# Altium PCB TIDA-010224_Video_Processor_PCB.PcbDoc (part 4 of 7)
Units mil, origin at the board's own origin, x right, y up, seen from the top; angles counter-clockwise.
Board outline 2355.46 x 4164 mil, 10 copper layers (L1-Top Layer, L2-GND, L3-SIG1, L4-GND, L5-PWR, L6-PWR, L7-GND, L8-SIG2, L9-GND, L10-Bottom Layer), stack 62.2 mil thick; 508 components, 274 nets, 3619 pads, 705 vias.
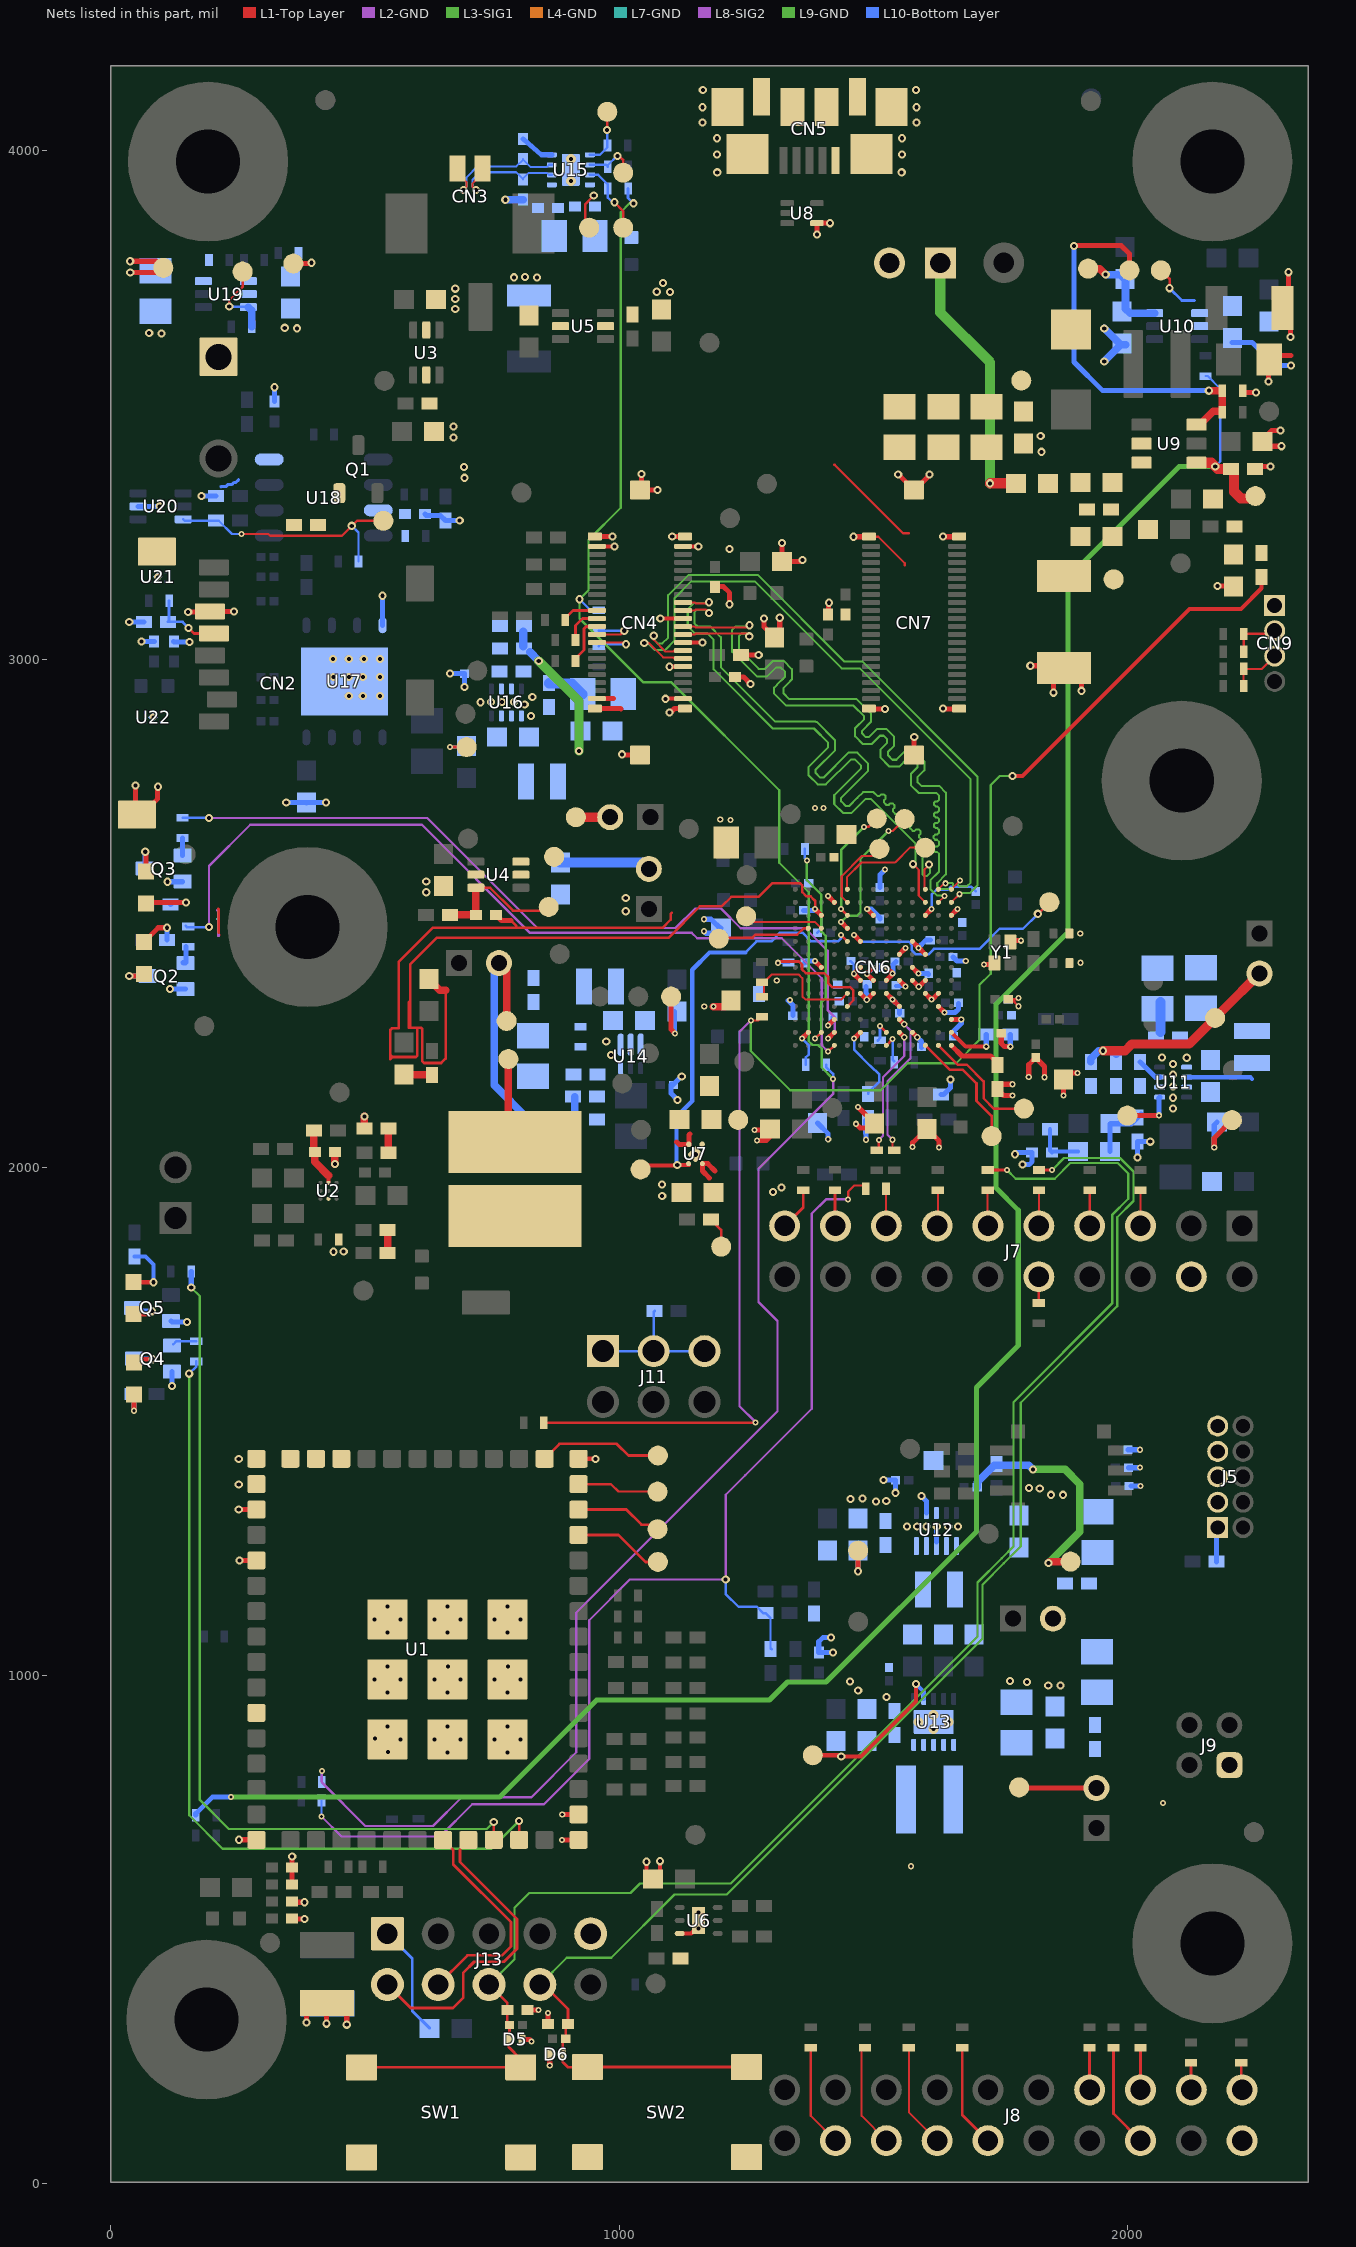
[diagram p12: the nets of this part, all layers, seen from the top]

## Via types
v1: diameter 16, hole 8, L1-Top Layer to L10-Bottom Layer, tented both sides, 414 vias
v2: diameter 12, hole 6, L1-Top Layer to L10-Bottom Layer, tented both sides, 243 vias
v3: diameter 19.68, hole 7.87, L1-Top Layer to L10-Bottom Layer, 44 vias
v4: diameter 14, hole 6, L1-Top Layer to L10-Bottom Layer, tented both sides, 2 vias
v5: diameter 16, hole 8, L1-Top Layer to L10-Bottom Layer, tented top, 1 vias
v6: diameter 20, hole 10, L1-Top Layer to L10-Bottom Layer, tented both sides, 1 vias

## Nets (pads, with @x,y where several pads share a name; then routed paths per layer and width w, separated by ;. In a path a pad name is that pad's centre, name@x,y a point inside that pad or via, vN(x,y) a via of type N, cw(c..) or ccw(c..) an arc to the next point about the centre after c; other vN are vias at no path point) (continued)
DEBUG_MAC: J13.4 U1.50 | length 439.2
  L1-Top Layer w5.5: J13.4@644,392 701.49,449.49 769.49,449.49 787,467 787,515 673.5,628.5 673.5,656.46 U1.50@653.26,676.7
DEBUG_NWP: J13.2 U1.51 | length 618.2
  L1-Top Layer w5.5: J13.2@544,392 590,346 672.8,346 693.4,366.6 693.4,415.4 715,437 773.51,437 799,462.49 799,521 687,633 687,658 703.26,674.26 U1.51@703.26,676.7
EFUSE_SW: CN6.J9 EN.1 U7.3 | length 855
  L1-Top Layer w5: v2(1436.77,2457) CN6.J9@1449,2444.77
  L1-Top Layer w8: EN.1@1042.21,1995.96 1049.79,2003.53 1113.53,2003.53 v1(1114.36,2004.36) U7.3@1137.4,2004.36
  L10-Bottom Layer w5: 1248.59,2423.13 1270.24,2444.77 1299.76,2444.77 1316.78,2461.79 1360.75,2461.79 1377.77,2444.77 1406.28,2444.77 1406.55,2445.04 1416.9,2445.04 1417.18,2444.77 1430.77,2444.77 1436.77,2450.77 v2(1436.77,2457)
  L10-Bottom Layer w8: v1(1114.36,2004.36) 1113.24,2003.24 1113.24,2099.78 1143.84,2130.39 1143.84,2388.85 1178.12,2423.13 1248.59,2423.13
FB: C55.2 FB.1 R67.1 R68.1 R72.2 U9.3
FREQ: FREQ.1 R78.2 R79.1 U9.6 | length 794.6
  L1-Top Layer w10: v1(1895.05,3813.16) 1895.88,3814 1987.56,3814 2004.08,3797.49 FREQ.1@2004.08,3765
  L1-Top Layer w15: U9.6@2136.13,3461.4 2142.4,3461.4 2169,3488 2187,3488 R78.2@2187,3528.24 v1(2160.24,3528.24)
  L10-Bottom Layer w10: v1(1895.05,3813.16) 1895,3584.87 1951.63,3528.24 v1(2160.24,3528.24)
GND: C3.2 C4.1 C5.1 C6.1 C7.2 C8.1 C11.2 C13.2 C14.2 C16.2 C17.1 C18.2 C19.1 C20.1 C21.2 C22.1 C23.2 C24.2 C25.2 C26.2 C27.2 C28.2 C29.2 C30.2 C31.1 C33.2 C34.2 C35.2 C36.2 C37.2 C38.2 C39.1 C40.2 C41.2 C42.2 C43.2 C44.2 C45.2 C46.2 C47.1 C48.1 C49.1 C50.1 C52.2 C53.1 C54.1 C56.1 C57.2 C58.2 C59.1 C60.1 C61.1 C62.2 C63.2 C64.2 C65.2 C66.2 C67.2 C68.2 C70.2 C71.1 C72.2 C73.2 C74.1 C75.1 C76.1 C77.1 C78.1 C79.1 C80.1 C81.1 C82.1 C83.1 C84.1 C85.1 C86.1 C87.2 C88.1 C89.2 C90.1 C91.1 C92.1 C93.2 C94.1 C95.2 C96.1 C97.1 C98.1 C99.1 C100.1 C101.1 C102.2 C103.1 C104.2 C105.1 C106.1 C107.1 C108.1 C109.2 C110.2 C111.2 C112.2 C113.2 C115.1 C116.2 C117.2 C118.1 C119.2 C120.2 C121.2 C123.1 C124.2 C125.2 C126.1 C127.2 C128.2 C129.1 C130.1 C131.1 C132.2 C133.2 C134.1 CN2.6 CN2.9 CN4.1 CN4.2 CN4.20 CN4.26 CN4.32 CN4.39 CN4.40 CN4.MP1 CN4.MP2 CN4.MP3 CN4.MP4 CN4.MP5 CN4.MP6 CN5.5 CN5.6 CN5.7 CN5.8 CN5.9 CN5.10 CN5.11 CN5.12 CN5.13 CN6.B4 CN6.C1 CN6.C10 CN6.D2 CN6.D5 CN6.E2 CN6.E3 CN6.E6 CN6.E7 CN6.E8 CN6.F3 CN6.F4 CN6.F5 CN6.F6 CN6.F7 CN6.F8 CN6.G4 CN6.G6 CN6.G7 CN6.G8 CN6.G11 CN6.H3 CN6.H5 CN6.J4 CN6.L1 CN6.L3 CN6.L7 CN6.L11 CN6.M10 CN7.MP1 CN7.MP2 CN7.MP3 CN7.MP4 CN7.MP5 CN7.MP6 CN9.1 D5.2 D6.2 J1.1 J5.3 J5.5 J5.7 J5.9 J7.22 J8.20 J9.1 J13.9 MK1.2 Q2.2 Q3.2 Q4.2 Q5.2 R4.1 R7.2 R33.1 R61.2 R64.1 R77.1 R78.1 R93.1 R94.1 R96.2 R97.2 R98.2 R106.2 R108.1 R110.1 R112.1 R113.1 R114.1 R116.2 R118.2 R120.1 R132.1 R135.2 R141.1 R148.1 R149.2 R172.1 SW1.2 SW1.4 SW2.2 SW2.4 U1.1 U1.2 U1.16 U1.25 U1.26 U1.27 U1.28 U1.29 U1.30 U1.32 U1.38 U1.43 U1.55@780.43,874.5 U1.56@780.43,992.61 U1.57@780.43,1110.72 U1.58@662.31,874.5 U1.59@662.31,992.61 U1.60@662.31,1110.72 U1.61@544.2,874.5 U1.62@544.2,992.61 U1.63@544.2,1110.72 U2.A2 U3.2 U3.5 U4.2 U5.2 U5.5 U6.3 U6.7 U7.2 U7.5 U8.4 U9.2 U10.2 U11.3 U11.5 U12.2 U12.3 U12.8 U13.8 U13.11@1619,908.87 U14.4@1003.12,2241.27 U15.4 U15.9@905,3962.97 U16.3 U16.5 U17.4 U17.9 U18.4 U19.2 U20.2 U21.5 U22.5 Y1.2 Y1.4 | length 9091.1
  L1-Top Layer w5: 210.89,2508.6 211.7,2507.79 211.7,2461.83 ; 658.57,2348.87 658.57,2214.22 649.72,2205.37 616.33,2205.37 612.35,2209.35 612.35,2272.46 610.26,2274.55 601.29,2274.55 ; 787,2485.76 797.97,2474.79 ; 1103.37,2500.68 1101.55,2498.86 1101.55,2487.7 1085.1,2471.25 632.81,2471.25 566.59,2405.03 566.59,2273.54 552.8,2273.54 549.75,2270.49 549.75,2221.16 ; v2(1385.59,2508.18) 1385.59,2524.27 1383.75,2526.11 1383.75,2526.31 1377,2533.06 1368.73,2533.06 1360.24,2541.55 1360.24,2554.77 1355.65,2559.36 1301.35,2559.36 1274.36,2532.37 1220.6,2532.37 1201.82,2513.59 1158.59,2513.59 1096.75,2451.75 640.89,2451.75 588.57,2399.43 588.57,2327.35 ; 1423.78,3382.57 1558.99,3247.36 1569.48,3247.36 ; CN7.MP1@1491.66,3240.91 1509.78,3240.91 1562,3188.69 1562,3185 ; C48.1@1765.5,2331 C48.1@1771.97,2331 ; v2(1785.97,2317) C48.1@1771.97,2331 ; v2(1785.97,2333.06) 1783.91,2331 C48.1@1771.97,2331 ; 549.75,2217.6 549.75,2221.16 ; 549.75,2217.6 549.75,2213.1 553.78,2217.13 ; 549.75,2217.6 550.22,2217.13 553.78,2217.13 ; 549.75,2221.16 553.78,2217.13 ; 553.78,2217.13 600.14,2217.13 602.95,2219.94 602.95,2272.89 601.29,2274.55 ; 588.57,2327.35 588.57,2275.59 589.55,2274.61 ; 588.57,2327.35 586.09,2324.87 586.09,2274.61 589.55,2274.61 ; 589.55,2274.61 594.88,2274.61 594.94,2274.55 601.29,2274.55
  L1-Top Layer w8: U1.16@920.19,1426.63 953.38,1426.63 v1(953.69,1426.31) ; CN4.1@959.29,3221.73 v1@990.66,3221.73 ; v1(1054.07,633.72) 1054.07,611.73 C24.2@1066.36,599.44 1080.65,613.72 v1(1080.65,634.72) ; v1(1081,3080) CN4.20@1128.58,3080 ; v1@1091.58,2922.52 CN4.40@1125.65,2922.52 ; v1(1099,2985) 1128.07,2985 CN4.32@1128.58,2985.51 ; U6.3@1119.17,492.36 1141.88,492.36 1150.95,501.44 U6.7@1156.77,501.44 ; CN4.26@1128.58,3032.76 v1(1164.17,3032.76) ; CN4.2@1128.58,3221.73 v1(1155.73,3221.73)
  L1-Top Layer w9: CN4.39@959.29,2922.52 989.41,2922.52
  L1-Top Layer w10: v1(48,2751.14) 48,2694.59 54.76,2687.83 92,2725.07 92,2748.42 v1(92.5,2748.93) ; v1(152,3093) 193.68,3093 CN2.6@194.65,3093.97 ; CN2.6@194.68,3094 v1(242,3094) ; v1(251.46,1326.67) 285,1326.67 285.67,1326 U1.30@286.07,1326.41 ; v1(252,677) 283.37,677 285,675.37 U1.43@286.33,676.7 ; v1(252.79,1226.67) U1.32@286.33,1226.67 ; C6.1@356,521.67 356.67,521 v1(381,521) ; C4.1@356,587 C4.1@356,589 356,619.67 356.67,619 v1(356.67,644) ; C5.1@366.36,554.33 366.69,554 v1(380.69,554) ; v1(385,317) 385,330.96 C7.2@395.97,341.93 ; v1(424,315) 424,332.78 429,337.78 C7.2@424.85,341.93 ; C7.2@457,341.93 464.02,334.91 v1(464.02,313) ; C19.1@757.25,2496.79 768.28,2485.76 787,2485.76 ; D5.2@808.42,284 823.88,284 v2(827.88,280) ; C20.1@819.37,342 v2(841.37,342) ; C22.1@860,314 v2(860,336) ; v2(863.41,233) D6.2@863.41,255 ; v2(887.81,676.45) U1.1@919.93,676.45 ; v2(888.07,726.67) U1.2@920.19,726.67 ; CN4.MP3@955.35,2902.83 1002.61,2902.83 1003.4,2902.04 ; CN4.MP1@955.35,3241.42 v1@986.73,3241.42 ; v1(1005.3,2812.79) 1005.3,2811.3 CN4.MP6@1041,2811.3 ; v1@1043.93,3364.33 1043.93,3332.95 v1@1075.31,3332.95 ; v1(1099,2895.06) 1101.06,2895.06 1108.84,2902.83 CN4.MP4@1129.58,2902.83 CN4.MP4@1132.51,2902.83 ; v1@1104.53,3241.42 CN4.MP2@1129.58,3241.42 CN4.MP2@1132.51,3241.42 ; 1113.24,2049.71 1117.64,2045.31 U7.2@1137.2,2045.31 1137.2,2063.56 1139.1,2065.46 ; C30.2@1189,3142.63 1205.37,3142.63 1217.46,3130.54 1217,3130.07 1217.46,3129.61 v1(1217.46,3108) ; C29.2@1228.16,2964.71 1244.93,2964.71 v1(1258.41,2951.23) ; C28.2@1239.62,3008 v1(1274.57,3008) ; v2(1266,2073.7) 1294.7,2073.7 1296.64,2075.64 C36.2@1297.12,2075.16 1297.12,2060.21 1289.69,2052.79 v2(1271.22,2052.79) ; v1(1284.97,3080) 1284.97,3063.82 C37.2@1299,3049.79 ; C37.2@1305.48,3042.38 1316,3052.9 v1(1316,3081.44) ; v1(1320.47,3228.76) 1320.47,3192.31 C34.2@1320.19,3192.03 1357.87,3192.03 v1(1361.11,3195.27) ; v2(1385.59,2405.82) CN6.G11@1397.82,2393.59 ; v2(1385.59,2508.18) CN6.L11@1397.82,2495.95 ; v1(1389.09,3835.23) U8.4@1389.09,3857.82 v1(1414.95,3857.82) ; C40.2@1409.18,3087.43 1411.83,3090.07 1411.83,3111 v1(1412.68,3111) ; v2(1411.18,2279) CN6.C10@1423.41,2291.23 ; v2(1411.18,2533.77) CN6.M10@1423.41,2521.54 ; v1(1461,3240.91) CN7.MP1@1491.66,3240.91 ; v2(1465.98,2085.73) 1474.48,2077.23 1493,2077.23 C42.2@1502,2086.23 1502,2086.71 v2(1469.98,2118.73) ; CN6.E8@1474.59,2342.41 v2(1487.18,2329.82) ; CN6.F8@1474.59,2368 1462,2380.59 v2(1462,2381) CN6.G8@1474.59,2393.59 ; v2@1487.59,2329.82 CN6.E7@1500.18,2342.41 ; v2(1488.13,2508) CN6.L7@1500.18,2495.95 ; CN7.MP3@1491.66,2902.32 v1@1523.04,2902.32 ; CN6.F7@1500.18,2368 1487.39,2380.8 CN6.G7@1500.18,2393.59 ; CN6.E6@1525.77,2342.41 v2(1538,2330.18) CN6.D5@1551.36,2316.82 ; CN6.F6@1525.77,2368 v2@1538,2380.23 ; CN6.G6@1525.77,2393.59 v2(1538,2381.36) ; v1(1549.08,3363.6) 1580.68,3332 1611,3362.32 v1(1611,3363.6) ; CN6.F5@1551.36,2368 v2(1563.59,2355.77) ; CN6.H5@1551.36,2419.18 v2(1563.59,2431.41) ; CN6.B4@1576.95,2265.64 v2(1586.59,2256) ; CN6.F4@1576.95,2368 v2(1589.54,2355.41) ; CN6.G4@1576.95,2393.59 v2(1589.18,2381.36) ; CN6.J4@1576.95,2444.77 1589.04,2432.69 1589.14,2432.69 1589.14,2432.58 CN6.H3@1602.54,2419.18 ; v2(1577.53,2040.23) 1577.53,2048.67 1604.8,2075.95 C44.2@1606.08,2075.95 1613.25,2068.79 1613.03,2068.79 1629.53,2052.29 v2(1629.53,2038.73) ; CN7.MP6@1580.24,2810.79 CN7.MP6@1580.24,2811.3 1580.24,2846.56 v1(1580.68,2847) ; v2@1589.95,2355.41 CN6.F3@1602.54,2368 ; CN6.E3@1602.54,2342.41 v2(1614.77,2330.18) ; CN6.L3@1602.54,2495.95 v2(1614.77,2508.18) ; v2@1615.91,2330.18 CN6.E2@1628.13,2342.41 ; CN6.D2@1628.13,2316.82 v2(1640.36,2304.59) ; v1@1637.45,2902.32 CN7.MP4@1668.82,2902.32 ; v1@1637.45,3240.91 CN7.MP2@1668.82,3240.91 ; CN6.C1@1653.72,2291.23 v2(1673.1,2291.23) ; CN6.L1@1653.72,2495.95 v2(1665.95,2508.18) ; v2(1718,2399) 1735.03,2399 Y1.2@1738.36,2402.33 ; C47.1@1751.83,2263.64 1751.83,2243.88 1758.29,2237.42 v2(1769.62,2237.42) ; Y1.4@1769.86,2443.67 1772.19,2446 v2(1791,2446) ; v2(1774,2141.44) 1756.28,2141.44 R61.2@1744,2153.72 1753.79,2163.52 v2(1774,2163.52) ; v2(1806,2177.79) 1806,2202.09 C50.1@1814.64,2210.73 ; v1(1809,2987) 1835.03,2987 R64.1@1839,2990.97 ; C50.1@1820,2216.09 1820,2215.27 1837,2198.27 v2(1837,2177.37) ; v1(1855,2934) 1855,2960 R64.1@1863,2968 ; v2(1874,2141.44) C52.2@1874,2172.67 1887.28,2185.95 v2(1902,2185.95) ; v1(1909.62,2937.76) 1909.62,2961.62 R64.1@1914,2966 ; v1(2177.02,3144) 2207.65,3144 C60.1@2208.65,3142.99 C60.1@2208.65,3142.17 ; R78.1@2227,3525 v1(2252.82,3525) ; R77.1@2244.62,3379 v1(2282,3379) ; v1(2278,3546) 2278,3588.17 C58.2@2279,3589.17 2287.17,3597.34 2321.9,3597.34 ; v1(2301,3450) 2284,3450 2267,3433 2265.5,3433 2279.5,3419 v1(2303,3419) ; v1(2316.77,3761.44) 2316.77,3702.59 2305,3690.81 2304.96,3673.04 2321,3657 v1(2321,3634)
  L1-Top Layer w15: v1(440.68,2006.69) C8.1@440.68,2030 ; C11.2@498.76,2076.76 v1(498.76,2100.07) ; C17.1@625.96,2370.29 647.38,2348.87 658.57,2348.87 ; v2(1185.71,2316.23) 1208,2316.23 C33.2@1220.46,2328.69
  L2-GND w5: 209.39,2505.74 211.61,2503.52 211.61,2455.38
  L4-GND w6: 211.61,2493.46 211.61,2457.4 212.19,2456.82
  L7-GND w6: 209.89,2488.73 211.76,2486.86 211.76,2460.13 211.61,2460.28
  L9-GND w6: 211.04,2487.29 211.61,2486.72 211.61,2462.28
  L10-Bottom Layer w5: v2(1385.59,2508.18) 1397.59,2496.18 1397.59,2469.52 C101.1@1390.07,2462 ; C97.1@1455.01,2406 1455.07,2406 1462,2399.07 v2(1462,2381) ; v2(1614.77,2508.18) 1614.77,2536.79 1624.25,2546.27 1646.95,2546.27 1652.4,2551.73 1693.27,2551.73 C76.1@1702,2542.99
  L10-Bottom Layer w6: 216.23,3339.22 216.47,3339.46 225.97,3339.46 229.89,3343.38 237.44,3343.38 241.82,3347.76 245.68,3347.76 251.21,3353.29
  L10-Bottom Layer w8: v1(385,317) 385,330.96 409.1,355.06 C127.2@427.63,355.06 ; v1(424,315) 424,343.14 429,348.14 424.85,352.29 C127.2@427.63,355.06 ; v1(464.02,313) 464.02,344.76 453.72,355.06 C127.2@427.63,355.06 ; C88.1@1544.99,2357 1562.36,2357 v2(1563.59,2355.77)
  L10-Bottom Layer w10: v1(36,3073.44) C132.2@64.9,3073.44 ; U20.2@53.49,3300.76 v1(95.45,3300.76) ; v1(60,3035) 85.4,3035 C134.1@85.52,3035.12 ; v1(111,2562) 140.72,2562 Q3.2@141.13,2562.41 ; v1(116.44,2351) 146.82,2351 Q2.2@147,2350.82 ; Q5.2@118.4,1697.71 120.11,1696 v1(150,1696) ; v1(120.09,1569.72) Q4.2@120.09,1598.12 ; C131.1@123,3034.68 123.68,3034 v1(154.54,3034) ; v1(178.16,3321.35) R172.1@206.57,3321.35 ; C130.1@322,3507 v1(322,3535) ; v1(345,2718) 384.03,2718 C128.2@384.52,2717.5 385.02,2718 v1(423,2718) ; U17.4@534.52,3066.67 v1(534.52,3124.77) ; C126.1@617.94,3285.41 620.48,3282.87 648.17,3282.87 C125.2@658.25,3272.79 v1(686.25,3272.79) ; v1(667,2972) 695.48,2972 696,2971.48 R149.2@695.52,2971 v1(695.52,2945.19) ; C124.2@811,4023.37 846.87,3992.5 U15.4@867.6,3992.5 ; v1(1115,2132.62) 1101.99,2145.63 1101.99,2162.5 1103.54,2164.04 1105.58,2162 1122.72,2179.14 v1(1123.23,2179.14) ; v2(1167.01,2488.19) 1180.88,2488.19 C109.2@1199.29,2469.78 ; v2(1167.26,2464.59) 1171.11,2460.73 1190.23,2460.73 C109.2@1199.29,2469.78 ; C109.2@1200.5,2471 C109.2@1199.29,2469.78 ; v2@1332.79,2328.37 1341.74,2319.42 C106.1@1341.74,2298.62 ; C108.1@1362.99,2505.82 1383.23,2505.82 v2(1385.59,2508.18) ; C107.1@1365,2402.01 1368.81,2405.82 v2(1385.59,2405.82) ; C102.2@1390.52,2087.07 1411.36,2066.23 v2(1411.36,2055.29) ; v2(1411.18,2279) 1421.01,2288.83 C99.1@1421.01,2296 ; v1(1417.16,1074.66) 1400.79,1074.66 1392.79,1066.66 C103.1@1392.79,1045.39 v1(1420.79,1045.39) ; v2(1485.35,2054.32) 1485.35,2066.53 1485.13,2066.75 1485.13,2092.51 R120.1@1490,2097.38 ; C94.1@1485.98,2355.41 1485.98,2342.42 1487.18,2341.22 v2(1487.18,2329.82) ; v2(1488,2380.91) 1500.1,2393.01 C92.1@1512,2393.01 ; v2(1488.13,2508) 1495.79,2508 1496.22,2508.43 1513,2491.65 C91.1@1513,2488.99 ; C90.1@1513.15,2550.49 1513.15,2575.98 v2(1523.04,2585.87) ; v1@1520.6,1384.69 R116.2@1544.01,1384.69 v1(1544.01,1359.68) ; v2(1538,2381.36) 1538.56,2381.93 1538.56,2398.56 C85.1@1545.01,2405 ; C86.1@1551.99,2303 1551.99,2316.19 v2@1538.93,2329.25 ; v2(1586.59,2256) 1594.98,2247.61 C84.1@1594.98,2236 ; v2@1589.14,2432.69 1603.45,2447 C82.1@1612.01,2447 C82.1@1612.48,2447 ; v2(1589.18,2381.36) 1589.3,2381.24 1607.75,2381.24 C83.1@1609,2379.99 ; v1(1594.7,1353.13) 1604.49,1343.34 U12.2@1604.49,1319.65 ; U13.11@1619,917 U13.11@1619.87,917.87 ; U12.8@1624.17,1262.56 1624.17,1292.34 v5(1625.04,1293.21) ; R113.1@1633.62,2143 1638.43,2143 1652,2156.57 v1(1652,2173) ; v2(1640.36,2304.59) 1660.88,2304.59 1667.99,2311.7 C78.1@1667.99,2322 ; C81.1@1656.99,2414 1664.99,2406 v2(1682,2406) ; C80.1@1657.99,2258 1659,2259.01 1659,2269 1673.1,2283.1 v2(1673.1,2291.23) ; v2(1769.62,2237.42) R106.2@1769.62,2261 ; v1(1779,2025.79) 1782.21,2029 C71.1@1812.66,2029 1812.66,2011.22 1806.72,2005.29 v1(1793.96,2005.29) ; R98.2@2001.45,1444.38 v2(2024.5,1444.38) ; R97.2@2002.01,1409 v2@2021.2,1409 ; R96.2@2006.84,1373.38 v2(2026.03,1373.38) ; v1@2020,2019.14 R94.1@2020,2050.52 v1(2045.01,2050.52) ; R93.1@2025,2207.62 2055.28,2177.35 U11.3@2063.68,2177.35 ; C62.2@2206.42,3623.17 2245.51,3623.17 2290.67,3578 v1(2321.9,3578) ; v2@1538.93,2329.25 1538,2329.25 v2(1538,2330.18) v2@1538.93,2329.25
  L10-Bottom Layer w15: v1(776,3904) 810.69,3904 C123.1@811,3904.31 ; v1(1954.5,3586) C66.2@1986.84,3618.34 ; v1(1954.5,3650.68) C66.2@1986.84,3618.34 ; C66.2@1996.25,3618.34 C66.2@1986.84,3618.34
  other v1: 1526,958.1 1470.37,970.34 1844.37,980.34 1868.37,980.34 1802.37,987.19 1454.51,988.24 1768.74,989.63 1566.54,1293.21 1586.54,1293.21 1604.54,1293.21 1647.54,1293.21 1666.54,1293.21 1505.54,1342.69 1525.54,1343.69 1455.54,1347.69 1478.54,1348.69 1849.54,1355.69 1873.54,1355.69 1827.6,1368.24 1806.61,1369.24 251.46,1375.96 1520.31,1384.98 251.46,1426.31 438,1834 458,1834.42 1084.72,1943.65 1302.5,1951.28 1319.13,1960.74 1084.17,1966.01 2020.29,2019.14 2089.81,2116.16 2089.46,2136.98 2089.46,2159.05 2089.46,2182.29 2089.46,2203.29 2068,2216 2116.83,2215.73 984,2221 974.57,2247.37 1013,2504 1013,2529.79 620.38,2541.29 620.38,2562.29 826.42,2888.2 1523.04,2902.04 1637.45,2902.61 814.14,2911 726.86,2915.22 747.67,2915.57 769.74,2915.57 792.99,2915.57 1091.07,2922.01 829.13,2925.88 468,2927.68 495.6,2927.68 529.43,2927.68 438.26,2965 468,2965 495.6,2965 529.43,2965 437,2999.98 468,2999.98 497.53,2999.98 529.43,2999.98 1216.9,3216.5 990.66,3221.45 986.73,3241.13 1104.53,3241.13 1637.45,3241.19 1075.31,3332.67 695.34,3356.87 1044.22,3364.33 694.91,3377.87 1831,3408 674,3436 1829.5,3439 674.33,3458 99.27,3641 75.27,3642 366,3651 342,3652 677.53,3689 677.53,3709 1074,3723 1100,3722.69 677.53,3728.91 1086,3740 838,3751 793.26,3751.35 815,3752 1193,3958 1556,3958 1192.38,3993 1556.62,3993 1192.38,4025 1556.62,4025 1164,4056 1585,4056 1164,4086 1585,4086 1164.63,4120 1584.37,4120
  other v2: 1574.63,624.79 2070,749 2025.05,1409.38 1167.42,2316.23 1336,2329.38 1310.14,2367.42 1907.6,2402.63 1589.14,2431.41 1907.34,2459.84 1219.06,2683.77 1198.9,2684.37 1385.38,2707.01 1402.01,2707.01
  other v3: 1156.57,502.4 1156.57,533.9 662.31,848.91 780.42,848.91 545,850 569.79,874.5 636.72,874.5 687.91,874.5 754.83,874.5 806.02,874.5 520,876 1619,895.09 544.2,900.09 662.31,900.09 780.42,900.09 1589.47,908.87 1648.53,908.87 1619,922.65 544.2,967.02 662.31,967.02 780.42,967.02 518.61,992.61 569.79,992.61 636.72,992.61 687.91,992.61 754.83,992.61 806.02,992.61 544.2,1018.2 663.3,1018.2 781.41,1018.2 544.2,1085.13 662.31,1085.13 780.42,1085.13 518.61,1110.72 569.79,1110.72 636.72,1110.72 687.91,1110.72 754.83,1110.72 806.02,1110.72 544.2,1136.31 662.31,1136.31 780.42,1136.31 905,3941.32 905,3984.63
  other v4: 82.88,2885.99 92,3162
  other v6: 1150.2,2025.43
HOST_ON: R51.1 R129.2 R131.2 R160.2 | length 2338.1
  L1-Top Layer w4.5: v2(1450.53,1937) 1450.53,1952.1 1462.71,1964.29 R51.1@1485,1964.29
  L8-SIG2 w4.5: v2(414,722.97) 453.44,683.53 647.53,683.53 710.98,746.98 852.29,746.98 941,835.69 941,1109 1021,1189 v1(1209.63,1189) 1209.63,1355.85 1247.95,1394.17 1379,1525.22 1379,1909 1407,1937 v2(1450.53,1937)
  L10-Bottom Layer w4.5: v2@414.22,726.25 R160.2@414.22,754 ; R129.2@1287.92,1123 1297.79,1113.14 R131.2@1297.79,1054.47 ; R131.2@1297.79,1052.47 R131.2@1297.79,1054.47 ; R131.2@1300.79,1051.47 R131.2@1297.79,1054.47
  L10-Bottom Layer w5: v1(1209.63,1189) 1209.63,1160.84 1235,1135.47 1271,1135.47 1283.47,1123 R129.2@1287.92,1123
IR-CUT_N: C124.1 CN3.1 U15.3 | length 281.4
  L1-Top Layer w4: CN3.1@681.97,3975.57 CN3.1@681.97,3965.13 681.97,3956.08 699.98,3938.07 699.91,3938 699.91,3929.17 v1(693.74,3923)
  L10-Bottom Layer w4: v1(693.74,3923) 699.91,3929.17 699.91,3948.2 721.31,3969.59 797.59,3969.59 C124.1@811,3983 ; C124.1@811,3984 C124.1@811,3983 ; U15.3@867.6,3972.82 862.36,3972.82 858.04,3968.5 825.34,3968.5 811,3982.84 C124.1@811,3983
IR-CUT_P: C123.2 CN3.2 U15.2 | length 262.1
  L1-Top Layer w4: v1(718,3923) 711.76,3929.24 711.76,3936.16 731.19,3955.59 CN3.2@731.19,3965.13 CN3.2@731.19,3974.87
  L10-Bottom Layer w4: v1(718,3923) 711.41,3929.59 711.41,3943.43 726.07,3958.09 797.13,3958.09 C123.2@811,3944.23 ; C123.2@811,3943.69 C123.2@811,3944.23 ; U15.2@867.6,3953.13 861.71,3953.13 857.84,3957 822,3957 811,3946 C123.2@811,3944.23
IR_CUT_EN: R125.2 R139.1 R143.1 R159.2 | length 4336.6
  L3-SIG1 w4.5: v1(1028,3897) 1020.5,3897 1003,3879.5 1003,3298 939.59,3234.59 939.59,3135.58 v1(921.95,3117.94) 921.95,3080.01 1047.15,2954.82 1102.21,2954.82 1315.11,2741.91 1315.11,2599.37 1373.09,2541.39 1373.09,2248.23 1380.41,2240.91 1391.1,2240.91 1398.68,2233.33 1398.68,2196.32 v2(1421,2174)
  L8-SIG2 w4.5: v2(415.08,812.55) 415.08,789.5 500.54,704.03 633.5,704.03 690.18,760.72 827.27,760.72 915.46,848.91 915.46,1124.31 1311.44,1520.28 1311.44,1697.72 1274,1735.16 1274,1997.2 1421,2144.2 v2(1421,2174)
  L10-Bottom Layer w4.5: v1(921.95,3117.94) 943.82,3096.06 R143.1@959.7,3096.06
  L10-Bottom Layer w5: R159.2@414.86,790.65 414.86,812.34 v2(415.08,812.55) ; R125.2@1407.4,2201.95 1407.4,2197.68 1421,2184.08 v2(1421,2174)
  L10-Bottom Layer w5.5: R139.1@1017.6,3926 1017.6,3907.4 v1(1028,3897)
IR_LED_EN: LED_EN.1 R77.2 R90.1 R176.2 U9.4 | length 4503.1
  L1-Top Layer w20: U9.4@2136.13,3386.6 2165.4,3386.6 v1(2173,3379) 2177.65,3374.35 2208.43,3374.35 2210,3372.78 2210,3329.38 2223.02,3316.36 LED_EN.1@2251.32,3316.36
  L3-SIG1 w10: v2(235.99,760.72) 764.72,760.72 956,952 1296,952 1331.19,987.19 1406.97,987.19 1703,1283.22 1703,1567 1785.27,1649.27 1785.27,1915.85 1741.87,1959.25 1741.87,2321.37 1883,2462.5 1883,3160 2102,3379 v1(2173,3379)
  L10-Bottom Layer w4.5: R90.1@2154,3557 2158,3557 2183,3532 2183,3389 v1(2173,3379)
  L10-Bottom Layer w10: R176.2@166.92,725.33 166.92,728.21 199.43,760.72 v2(235.99,760.72)
KEY1: C20.2 D5.1 J13.6 R16.1 R60.1 SW1.1 SW1.3 | length 3133.9
  L1-Top Layer w5.5: SW1.1@503.24,229.15 SW1.3@806.24,229.15 806.24,245.76 782.83,269.17 ; J13.6@744,392 780,356 C20.2@780,342 R16.1@780,316.51 ; R16.1@780,316.01 R16.1@780,316.51 ; 782.83,270.17 D5.1@782.83,284 D5.1@782.83,288 ; D5.1@784.01,288.18 R16.1@784.01,312 ; R16.1@784.01,312.5 R16.1@780,316.51 ; R60.1@1725.14,1994.84 v2(1763.23,1994.86)
  L3-SIG1 w4.5: J13.6@744,392 794,442 794,543 823,572 1022.27,572 1041.27,591 1219.41,591 1705,1076.59 1705,1183 1752.82,1230.82 1776,1254 1776,1538 1970,1732 1970,1906.14 2001.88,1938.03 2001.88,1987.78 1981.22,2008.44 1887.6,2008.44 1856.95,1977.79 1780.31,1977.79 v2(1763.23,1994.86)
KEY2: C22.2 D6.1 J13.8 R22.1 R66.1 SW2.1 SW2.3 | length 2963.5
  L1-Top Layer w5.5: J13.8@844,392 851,392 899.37,343.63 C22.2@899.37,314 895,309.63 R22.1@895,285.7 889,279.7 D6.1@889,255 889,240 899.85,229.15 SW2.1@949.98,229.15 ; SW2.1@947.5,229.58 SW2.3@1250.5,229.58 SW2.3@1260.5,229.58 ; R66.1@1826.24,1994.84 1851.84,1994.84 v2(1852,1995)
  L3-SIG1 w4.5: J13.8@844,392 897,445 984.63,445 1108.7,569.07 1192,569.07 1211.62,569.07 1393.41,750.86 1715,1072.45 1715,1178.86 1756.96,1220.82 1790,1253.86 1790,1537 1980,1727 1980,1902 2011.88,1933.88 2011.88,1991.92 1985.37,2018.44 1875.44,2018.44 v2(1852,1995)
LED_A: R178.1 U1.53 | length 1635.2
  L1-Top Layer w5: U1.53@803.26,676.7 v1@803.26,714
  L3-SIG1 w4.5: v1(154,1594) 154,725 220,659 748,659 v1(803,714)
  L10-Bottom Layer w5: v1(154,1594) 168,1608 R178.1@168,1618
LED_B: R180.1 U1.52 | length 1690
  L1-Top Layer w5: U1.52@753.26,676.7 v1(753.26,712)
  L3-SIG1 w4.5: v1(158,1763.28) 175,1746.28 175,755 232,698 739.26,698 v1(753.26,712)
  L10-Bottom Layer w10: v1(158,1763.28) R180.1@158,1795
LED_C: CN6.B10 R181.1 | length 1610.4
  L1-Top Layer w10: v2(1411.18,2253.41) CN6.B10@1423.41,2265.64
  L8-SIG2 w4.5: v1(193,2687.52) 622.38,2687.52 838.91,2471 1111.1,2471 1149.51,2509.42 1200.27,2509.42 1239.33,2470.36 1366.21,2470.36 1410.22,2426.35 1410.22,2309.54 1423.96,2295.79 1423.96,2266.19 v2(1411.18,2253.41)
  L10-Bottom Layer w5: R181.1@141,2688 v1@193,2688
LED_D: CN6.A10 R179.1 | length 1698
  L1-Top Layer w5.5: v2(1411.18,2227.82) CN6.A10@1423.41,2240.05
  L8-SIG2 w4.5: v1(193,2472.63) 193,2593 274,2674 611.95,2674 824.58,2461.37 1142.9,2461.37 1153.58,2450.69 1319.87,2450.69 1398.57,2372 1398.57,2240.43 v2(1411.18,2227.82)
  L10-Bottom Layer w5: R179.1@147.3,2475 149.67,2472.63 v1(193,2472.63)
LED_PWM: R17.2 R46.1 R85.1 | length 3059
  L1-Top Layer w4.5: R17.2@852,1497.61 v2(1268.1,1497.61) ; v2@1264.01,2288.9 1273.1,2288.9 1280.2,2296 R46.1@1281,2296
  L1-Top Layer w8: v1(1774.34,2770) 1794,2770 2122.69,3098.69 2223.33,3098.69 2264.15,3139.51 R85.1@2264.15,3161.87
  L3-SIG1 w4.5: v2(1259.1,2289) 1259.1,2229.13 1336.69,2151.54 1514.54,2151.54 1568,2205 1663.25,2205 1709.25,2251 1709.25,2359.25 1731.12,2381.12 1731.12,2752.12 1749,2770 v1(1774.34,2770)
  L8-SIG2 w4.5: v2(1259.1,2289) 1236.86,2266.75 1236.86,1530.13 1268.1,1498.88 v2(1268.1,1497.61)
MRXCN0: CN4.24 CN6.N2 | length 1187.5
  L1-Top Layer w4: CN4.24@1128.58,3048.5 1148.29,3048.5 1150.42,3050.63 v1@1252.22,3050.63 ; CN6.N2@1628.13,2547.13 1640,2559 v2(1642,2559)
  L3-SIG1 w4: v1(1256,3045) 1250.25,3050.75 1240.84,3050.75 1236,3045.91 1236,3019.38 1274.38,2981 1287,2981 1302.72,2996.72 1323.69,2996.72 1340,2980.41 1340,2959.91 1330.5,2950.41 1330.41,2950.41 1323.64,2943.64 1323.64,2932.45 1334.61,2921.48 1467.18,2921.48 1495.5,2893.16 1495.5,2876.45 1478,2858.95 1478,2853.75 1485.25,2846.5 1491.41,2846.5 1507.72,2862.81 1525.84,2862.81 1541,2847.66 1541,2829.76 1529.06,2817.82 1529.06,2810.62 1537.59,2802.09 1545.25,2802.09 1561.68,2818.53 1580.57,2818.53 1600.38,2798.71 1600.38,2781.29 1587.5,2768.41 1587.5,2757.59 1594.59,2750.5 1629.63,2750.5 1643,2737.13 1643,2576.52 1625.91,2559.43 1625.91,2553.28 1631.14,2548.05 1655.03,2548.05 1657,2550.01 1657,2558 1655,2560 1643,2560 v2(1642,2559)
MRXCP0: CN4.22 CN6.M2 | length 1267.9
  L1-Top Layer w4: CN4.22@1128.58,3064.25 1148.29,3064.25 1150.42,3062.13 1251.89,3062.13 v1(1256.44,3066.67) ; CN6.M2@1628.13,2521.54 v2(1640.36,2533.77)
  L3-SIG1 w4: v1(1256.44,3066.67) 1254.93,3065.16 1254.02,3064.25 1229.25,3064.25 1222.5,3057.5 1222.5,3014.5 1271,2966 1291.09,2966 1308.31,2983.22 1318.1,2983.22 1326.5,2974.82 1326.5,2965.5 1324.91,2963.91 1324.82,2963.91 1310.14,2949.23 1310.14,2949.05 1305,2943.91 1305,2932 1328.5,2908.5 1329.21,2908.5 1461.09,2908.48 1482,2887.57 1482,2882.05 1464.5,2864.55 1464.5,2848.16 1479.66,2833 1497,2833 1513.31,2849.31 1520.25,2849.31 1527.5,2842.07 1527.5,2835.35 1514,2821.85 1514,2806.59 1532,2788.59 1550.84,2788.59 1567.27,2805.03 1574.97,2805.03 1586.88,2793.12 1586.88,2786.88 1574,2774 1574,2752 1589,2737 1624.04,2737 1629.53,2731.51 1629.53,2723.53 1626.34,2720.34 1622.43,2720.34 1619.47,2717.38 1619.47,2713.42 1622.61,2710.28 1626.1,2710.28 1629,2707.38 1629,2701.38 1626.34,2698.72 1622.43,2698.72 1619.47,2695.76 1619.47,2691.8 1622.61,2688.66 1626.1,2688.66 1629,2685.76 1629,2680.38 1626.34,2677.72 1622.43,2677.72 1619.47,2674.76 1619.47,2670.8 1622.61,2667.66 1626.1,2667.66 1629,2664.76 1629,2658.22 1625.5,2654.72 1621.59,2654.72 1618.64,2651.76 1618.64,2647.8 1621.77,2644.66 1625.27,2644.66 1629.53,2640.4 1629.53,2635.05 1625.5,2631.02 1621.59,2631.02 1618.64,2628.07 1618.64,2624.1 1621.77,2620.97 1625.27,2620.97 1629.53,2616.7 1629.53,2582.14 1612.41,2565.02 1612.41,2547.69 1625.55,2534.55 1639.59,2534.55 v2(1640.36,2533.77)
MRXDN0: CN4.30 CN6.N1 | length 1272.1
  L1-Top Layer w4: v1(1049.37,3031.84) 1058.05,3031.84 1086.5,3003.38 1106.74,3003.38 1108.86,3001.26 CN4.30@1125.65,3001.26 CN4.30@1128.58,3001.26 ; CN6.N1@1653.72,2547.13 1670.3,2563.7 v2(1670.3,2564.23)
  L3-SIG1 w4: v1(1049.37,3031.84) 1056.61,3031.84 1070.44,3018 1090.38,3018 1109.33,3036.94 1109.33,3120.38 1141.94,3153 1267.01,3153 1438.01,2982 1473.02,2982 1691.5,2763.52 1691.5,2560.19 1684.31,2553 1669.59,2553 1666.54,2556.05 1666.54,2560.47 v2(1670.3,2564.23)
MRXDN1: CN4.18 CN6.N3 | length 1267.5
  L1-Top Layer w4: CN4.18@1128.58,3095.75 1148.29,3095.75 1150.42,3097.87 1170.13,3097.87 v1(1177,3091) ; CN6.N3@1602.54,2547.13 1601,2548.68 1601,2586.81 v1(1610,2595.81)
  L3-SIG1 w4: v1(1177,3091) 1177,3092.45 1172.6,3096.84 1152.52,3096.84 1148,3092.32 1148,3070.46 1154.21,3064.25 1179.02,3064.25 1200,3043.27 1200,2984.29 1307.29,2877 1386.76,2877 1387.26,2876.5 1388.74,2876.5 1424.36,2840.88 1424.36,2839.4 1424.86,2838.9 1424.86,2821.06 1386.31,2782.51 1386.31,2776.69 1396,2767 1402.01,2767 1451.01,2816 1468.57,2816 1489.5,2795.07 1489.5,2779.5 1459.59,2749.59 1459.46,2749.59 1436.77,2726.9 1436.77,2720.23 1446,2711 1452.55,2711 1468.55,2727 1468.55,2727.1 1468.64,2727.1 1480.05,2738.5 1500.5,2738.5 1507.92,2731.08 ; 1508.62,2731 1512.62,2731 1515.75,2734.12 1520.87,2734.12 1524.25,2730.75 1524.25,2725.62 1521.25,2722.62 1521.25,2717.75 1526,2713 1530,2713 1533.12,2716.12 1538.25,2716.12 1541.62,2712.75 1541.62,2707.62 1538.62,2704.62 1538.62,2700.38 1543.24,2695.76 1547.24,2695.76 1550.36,2698.88 1555.48,2698.88 1558.86,2695.51 1558.86,2690.38 1555.86,2687.38 1555.86,2683.14 1560,2679 1564,2679 1567.12,2682.12 1572.25,2682.12 1575.62,2678.75 1575.62,2673.62 1572.62,2670.62 1572.62,2666.91 1577.53,2662 1581.53,2662 1584.65,2665.12 1589.77,2665.12 1593.15,2661.75 1593.15,2656.62 1590.15,2653.62 1590.15,2649.38 1597,2642.53 1597,2576.13 1599.52,2573.61 1606.19,2573.61 1612,2579.42 1612,2593.81 v1(1610,2595.81)
MRXDP0: CN4.28 CN6.M1 | length 1275
  L1-Top Layer w4: v1(1068.07,3046) 1068.07,3038.08 1091.26,3014.88 1106.74,3014.88 1108.86,3017.01 CN4.28@1125.65,3017.01 CN4.28@1128.58,3017.01 ; CN6.M1@1653.72,2521.54 1669.68,2537.5 v2(1670,2537.5)
  L3-SIG1 w4: v1(1068.07,3046) 1068.07,3038.76 1075.83,3031 1085,3031 1096.33,3042.33 1096.33,3125.77 1136.56,3166 1272.4,3166 1443.4,2995 1479.11,2995 1705,2769.11 1705,2554.59 1690.63,2540.23 1689.93,2540.23 1689.7,2540 1672.5,2540 v2(1670,2537.5)
MRXDP1: CN4.16 CN6.M3 | length 1189.5
  L1-Top Layer w4: CN4.16@1128.58,3111.5 1148.29,3111.5 1150.42,3109.37 v1@1173.66,3109.37 ; v1(1578.46,2596.54) 1589.5,2585.51 1589.5,2534.59 CN6.M3@1602.54,2521.54
  L3-SIG1 w4: v1(1177,3112) 1176.29,3112 1174.64,3110.34 1146.93,3110.34 1136,3099.42 1136,3098.71 1135,3097.71 1135,3065.08 1136,3064.08 1136,3063.37 1148.62,3050.75 1173.43,3050.75 1186,3038.18 1186,2979.91 1302.41,2863.5 1383.36,2863.5 1411.36,2835.5 1411.36,2826.68 1372.81,2788.13 1372.81,2771.1 1390.41,2753.5 1406.9,2753.5 1456.4,2803 1463.19,2803 1476,2790.19 1476,2785.09 1454,2763.09 1453.87,2763.09 1423.27,2732.49 1423.27,2714.64 1440.41,2697.5 1457.5,2697.5 1485,2725 1495,2725 1583.5,2636.5 1583.5,2601.58 v1(1578.46,2596.54)
Net1.1V_1: 1.1V.1 C114.1 C116.1 J14.2 L5.2 R142.2 R146.2 | length 592.4
  L1-Top Layer w15: J14.2@763.37,2402 778.5,2386.87 1.1V.1@778.5,2288
  L10-Bottom Layer w15: J14.2@750.37,2401.1 754,2397.47 754,2162.08 822.08,2094 C114.1@909.38,2094 912.38,2094 R142.2@912.38,2139
Net1.8V_1: 1.8V.1 C112.1 C122.1 J12.2 L6.2 R145.2 R147.2 | length 331.1
  L1-Top Layer w18: 1.8V.1@914.89,2689.02 J12.2@982.46,2689.02
  L3-SIG1 w18: v1(841.85,2996.43) 921.19,2917.09 v1(921.19,2819.42)
  L10-Bottom Layer w16: R147.2@811.39,3025.28 C122.1@811.39,3054 ; R147.2@824.23,3014.05 v1(841.85,2996.43)
Net1.35V_1: 1.35V.1 C64.1 C69.1 J6.2 L2.2 R92.2 R99.2 | length 437.9
  L1-Top Layer w10: 1.35V.1@2172.62,2294 2188,2309.38
  L1-Top Layer w18: v1(1951.93,2229.42) 1995.62,2229.42 2009,2242.79 2121.42,2242.79 1.35V.1@2172.62,2294 ; 2188,2309.38 J6.2@2260,2381.38
  L10-Bottom Layer w15: C69.1@1928,2207.76 1928,2214 1943.42,2229.42 v1(1951.93,2229.42) 1967.65,2229.42 1970.07,2227 1972.07,2229 R99.2@1977.99,2223.08
Net2.5V_1: 2.5V.1 C26.1 R42.1 U7.1
Net3.3V_1: 3.3V.1 C117.1 J2.2 U4.5 U4.6 | length 179.5
  L10-Bottom Layer w20: C117.1@884.12,2600.08 1045.64,2600.08 J2.2@1058.35,2587.37
NetC8_2: C8.2 R5.2 U2.C2 | length 115.2
  L1-Top Layer w8: U2.C2@428.07,1969.68 428.07,1983.93
  L1-Top Layer w15: R5.2@399.38,2073 399.38,2031.94 C8.2@401.31,2030 401.31,2010.69 428.07,1983.93
NetC10_1: C10.1 R9.1 | length 48.7
  L1-Top Layer w15: C10.1@544.56,1831.47 545,1831.91 R9.1@545,1880
NetC11_1: C11.1 R10.1 | length 48
  L1-Top Layer w15: R10.1@545.5,2024.91 C11.1@545.5,2072.91
NetC15_2: C15.2 MIC_IN.1 MK1.1 R14.1 | length 227.2
  L1-Top Layer w15: C15.2@576.34,2182.3 631.21,2182.3 R14.1@631.34,2182.17 R14.1@631.34,2178.93 ; MIC_IN.1@781.95,2213.1 781.95,2062.7 MK1.1@795,2049.65
NetC19_2: C19.2 ON.1 R13.2 U4.3 | length 268.9
  L1-Top Layer w5: U4.3@718,2550.2 746.09,2550.2 791.13,2505.15 854.21,2505.15 ON.1@861.43,2512.38
  L1-Top Layer w10: C19.2@717.67,2497 C19.2@717.88,2496.79
  L1-Top Layer w15: R13.2@667.62,2497 C19.2@717.67,2497 ; C19.2@717.88,2496.79 718,2496.9 U4.3@718,2550.2
NetC27_1: C27.1 IN_2.5V.1 R41.1 U7.4 | length 125.8
  L1-Top Layer w5: R41.1@1180.62,1897 1200.83,1876.79 IN_2.5V.1@1200.83,1844.07
  L1-Top Layer w10: 1177.32,1979.39 1163.8,1992.91 U7.4@1163.8,2007.34 1174.32,2007.34 1188.76,1992.91
NetC43_1: C43.1 C45.1 C46.1 C49.2 CN8.1 D8.1 LED_OUT.1 R62.2 | length 524.7
  L1-Top Layer w20: v1(1730,3346) R62.2@1780.5,3346
  L3-SIG1 w20: CN8.1@1631.88,3779.51 1631.88,3682.12 1730,3584 v1(1730,3346)
NetC55_1: C55.1 R62.1 R67.2
NetC60_2: C60.2 R76.1 R85.2
NetC62_1: C62.1 IN_PS.1 R86.2 U10.1 | length 100.9
  L1-Top Layer w5.5: IN_PS.1@2066,3765 2083.26,3747.74 v1(2083.26,3729.92)
  L10-Bottom Layer w5.5: v1(2083.26,3729.92) 2107.18,3706 2132,3706
NetC63_1: C63.1 IN_1.35V.1 R87.2 U11.7 | length 119.5
  L1-Top Layer w10: v2(2171,2039.4) 2171,2058 IN_1.35V.1@2206,2093
  L10-Bottom Layer w10: v2@2171,2039.63 2171,2083.65 R87.2@2176.25,2088.89
NetC65_1: C65.1 R92.1 | length 58.4
  L10-Bottom Layer w20: R92.1@2064.93,2267 C65.1@2064.93,2325.38
NetC66_1: C66.1 OUT_PS.1 R95.1 U10.6 | length 201.5
  L1-Top Layer w15: OUT_PS.1@1922.87,3768.45 1945.48,3768.45 v1(1957.37,3756.56)
  L10-Bottom Layer w15: v1(1957.37,3756.56) 1986.43,3756.56 1995.21,3747.78 R95.1@1995.73,3748.3 1996.25,3747.78 1996.25,3689.84 2005.33,3680.76 U10.6@2053.71,3680.76
NetC67_1: C67.1 R103.1
NetC68_1: C68.1 R102.1
NetC69_2: C69.2 R93.2 R99.1 U11.2
NetC70_1: C70.1 C72.1 J4.2 R102.2 U13.6 VOUT2.1 | length 152.6
  L1-Top Layer w10: VOUT2.1@1786.96,780 1788.22,778.74 J4.2@1939,778.74
NetC71_2: C71.2 R101.1 R105.1 | length 99.3
  L10-Bottom Layer w8: R105.1@1848,2075 1848,2033.03 C71.2@1852.03,2029 1853.86,2030.84 R101.1@1902.93,2030.84
NetC73_1: C73.1 J10.2 R103.2 R107.2 R109.2 U12.6 VOUT1.1 | length 465.6
  L1-Top Layer w15: v1(1844.89,1221.76) 1847.41,1224.28 VOUT1.1@1888.26,1224.28
  L3-SIG1 w15: v1(1814.36,1405.68) 1877.32,1405.68 1906.27,1376.73 1906.27,1283.15 v1(1844.89,1221.76)
  L10-Bottom Layer w15: R109.2@1704.52,1370.75 1704.52,1380.41 1738.1,1414 1806.04,1414 v1(1814.36,1405.68)
NetC87_1: C87.1 C93.1 IN2.1 R123.2 U13.2 U13.10 | length 319.3
  L1-Top Layer w8: IN2.1@1381,843.22 1434.34,843.22 v1(1437.08,840.48) 1476.05,840.48 1584.37,948.8 v1(1584.37,983.34)
  L10-Bottom Layer w8: v1(1584.37,983.34) 1599.31,968.4 U13.2@1599.31,954.15
NetC89_1: C89.1 C95.1 IN1.1 R124.2 U12.10 | length 81
  L1-Top Layer w10: v1(1470.17,1205.24) IN1.1@1470.17,1245.72
  L10-Bottom Layer w10: v1(1470.17,1205.24) C95.1@1470.17,1245.72
NetC110_1: C110.1 IN_1.1V.1 R134.2 U14.6@1042.48,2241.47 | length 117.8
  L1-Top Layer w10: IN_1.1V.1@1102.32,2336 1102.32,2271.29 v2(1110,2263.61)
  L10-Bottom Layer w10: v2@1108.49,2264.24 R134.2@1108.49,2306.45
NetC111_1: C111.1 R145.1 | length 75.8
  L10-Bottom Layer w20: R145.1@862,2952.62 872.62,2952.62 872.2,2952.2 906.8,2952.2 C111.1@928,2931
NetC113_1: C113.1 C115.2 C118.2 FB11.2 U15.1 U15.8 VCC_IR.1 | length 70
  L1-Top Layer w5: VCC_IR.1@933,3849 933,3895 v1(950,3912)
NetC114_2: C114.2 R141.2 R142.1 U14.3
NetC120_1: C120.1 R146.1
NetC121_1: C121.1 IN_1.8V.1 R150.2 U16.7 | length 66.8
  L1-Top Layer w5.5: v2(666.78,2827) IN_1.8V.1@700,2827
  L10-Bottom Layer w5.5: v2(666.78,2827) 697.81,2827 R150.2@699.59,2828.78
NetC122_2: C122.2 R147.1 R148.2 U16.2
NetC126_2: C126.2 R153.1 U18.7
NetC129_2: C129.2 PS_VCC.1 R162.2 U19.1 | length 36.7
  L1-Top Layer w10: PS_VCC.1@358.9,3778.47 393.47,3778.47 v1(395,3780)
NetC132_1: C132.1 CN2.5 R184.1 | length 142.4
  L1-Top Layer w5.5: v1(152.86,3061.14) 163.34,3050.66 CN2.5@202.52,3050.66
  L10-Bottom Layer w5.5: R184.1@114.52,3115 114.52,3075.81 C132.1@112.14,3073.44 140.56,3073.44 v1(152.86,3061.14)
NetC133_1: C133.1 R174.1 U19.6 VCC_AMP.1 | length 139.2
  L1-Top Layer w10: v1(37.87,3783) 90,3783 VCC_AMP.1@103,3770 94,3761 v1(38,3761)
NetC_1: C.1 CN6.K12 | length 178.8
  L1-Top Layer w5: C.1@1201,2452 1262.36,2452 1268.22,2457.86 1350.43,2457.86 1362.93,2470.36 CN6.K12@1372.23,2470.36
NetCLK_1: CLK.1 CN6.M9 | length 152.3
  L1-Top Layer w4: CN6.M9@1449,2521.54 1437.98,2532.56 1437.98,2573.19 1477.79,2613 1498.42,2613 CLK.1@1512,2626.58
NetCN4_17: CN4.17 R21.2 | length 75.3
  L1-Top Layer w5.5: R21.2@894.19,3076.86 894.19,3081 908.94,3095.75 CN4.17@956.35,3095.75 CN4.17@959.29,3095.75
NetCN4_19: CN4.19 R23.2 | length 79.4
  L1-Top Layer w5.5: R23.2@914.19,3037.53 914.19,3066.05 928.14,3080 CN4.19@956.35,3080 CN4.19@959.29,3080
NetCN4_21: CN4.21 R24.2 | length 100.5
  L1-Top Layer w5.5: R24.2@914.19,2996.53 914.19,3001.19 930.75,3017.75 930.75,3059.86 935.14,3064.25 CN4.21@956.35,3064.25 CN4.21@959.29,3064.25
NetCN4_23: CN4.23 R143.2 | length 104.6
  L1-Top Layer w4.5: CN4.23@959.29,3048.5 1002.55,3048.5 v1(1009.97,3055.93)
  L10-Bottom Layer w4.5: R143.2@959.7,3056.06 1010.32,3056.06 v1@1010.46,3055.93
NetCN4_25: CN4.25 R144.2 | length 110.7
  L1-Top Layer w4.5: CN4.25@959.29,3032.76 1009.81,3032.76 v1(1013.28,3029.29)
  L10-Bottom Layer w4.5: R144.2@959.7,3025.2 963.79,3029.29 v1(1013.28,3029.29)
NetCN6_A1: CN6.A1 R61.1 | length 109.4
  L1-Top Layer w10: CN6.A1@1653.72,2240.05 1674.77,2219 1731,2219 1744,2206 R61.1@1744,2200.97
NetCN6_A2: CN6.A2 DBG1.1 | length 245
  L1-Top Layer w5: CN6.A2@1628.13,2240.05 1666.18,2202 1683.99,2202 1717,2168.99 1717,2136 1738,2115 DBG1.1@1802,2115
NetCN6_A3: CN6.A3 DBG0.1 | length 247.7
  L1-Top Layer w5: CN6.A3@1602.54,2240.05 1650.68,2191.91 1676.44,2191.91 1703.14,2165.21 1703.14,2131 1733,2101.14 DBG0.1@1733,2061.48
NetCN6_A6: CN6.A6 R115.1 | length 61.8
  L1-Top Layer w5.5: CN6.A6@1525.77,2240.05 v2(1538,2252.28)
  L10-Bottom Layer w5.5: v2(1538,2252.28) 1538.5,2251.78 1538.5,2211.57 R115.1@1541.07,2209
NetCN6_B1: CN6.B1 R106.1 | length 103.9
  L1-Top Layer w8: CN6.B1@1653.72,2265.64 1681.94,2237.42 v2(1722.38,2237.42)
  L10-Bottom Layer w10: v2(1722.38,2237.42) R106.1@1722.38,2261
NetCN6_B5: CN6.B5 R52.1 | length 256.5
  L1-Top Layer w4.5: R52.1@1511,2033.86 v2(1511,2054)
  L1-Top Layer w10: CN6.B5@1551.36,2265.64 v2(1561,2256)
  L8-SIG2 w4.5: v2(1511,2054) 1519.19,2062.19 1519.19,2177.41 1561,2219.22 v2(1561,2256)
NetCN6_B6: CN6.B6 R119.1 | length 47.3
  L1-Top Layer w5.5: v2(1513.54,2277.87) CN6.B6@1525.77,2265.64
  L10-Bottom Layer w5.5: R119.1@1509,2249.78 1513.54,2254.33 v2(1513.54,2277.87)
NetCN6_B8: CN6.B8 R120.2 | length 156
  L1-Top Layer w10: v2(1462.36,2253.41) CN6.B8@1474.59,2265.64
  L10-Bottom Layer w5: v2(1462.36,2253.41) 1462.36,2231.59 1494.14,2199.81 1494.5,2199.81 1512,2182.31 1512,2168.86 1490,2146.86 R120.2@1490,2144.62
NetCN6_B11: CN6.B11 R126.1 | length 416.1
  L1-Top Layer w5: v2(1385.59,2253.41) CN6.B11@1397.82,2265.64
  L3-SIG1 w5: v2(1369.56,2603.95) 1369.56,2564.96 1398.09,2536.43 1398.09,2463.86 1406.56,2455.39 1406.56,2333.83 1398.09,2325.37 1398.09,2265.91 v2(1385.59,2253.41)
  L10-Bottom Layer w5: R126.1@1365.58,2626.58 1365.58,2607.93 v2(1369.56,2603.95)
NetCN6_B12: CN6.B12 R125.1 | length 76.8
  L1-Top Layer w10: v2(1360,2253.41) CN6.B12@1372.23,2265.64
  L10-Bottom Layer w5: v2(1360,2253.41) 1373.25,2240.16 1373.25,2233.15 1373.09,2233 1373.09,2222.64 1373.25,2222.48 1367.4,2216.64 R125.1@1367.4,2201.95
NetCN6_C5: CN6.C5 R53.1 | length 288.5
  L1-Top Layer w4.5: R53.1@1537.94,2034.5 v2(1537.94,2054.32)
  L1-Top Layer w10: CN6.C5@1551.36,2291.23 v2(1561,2281.59)
  L8-SIG2 w4.5: v2(1537.94,2054.32) 1528.19,2064.08 1528.19,2169.66 1573.25,2214.73 1573.25,2269.34 v2(1561,2281.59)
NetCN6_D9: CN6.D9 R130.2 | length 242.1
  L1-Top Layer w5: v2(1312.47,2402.55) 1315.03,2405.11 1353.61,2405.11 1359.8,2398.92 1359.8,2389.45 1367.24,2382 1404,2382 1411,2375 1411,2363.18 1420.18,2354 1455,2354 1461,2348 1461,2328.82 CN6.D9@1449,2316.82
  L10-Bottom Layer w5: v2@1314.16,2403 R130.2@1333,2403 R130.2@1334.41,2403
NetCN6_E9: CN6.E9 R45.2 R46.2 | length 249.6
  L1-Top Layer w4: R46.2@1281,2336 1285,2340 1285,2364 R45.2@1281,2364 ; R45.2@1286,2365 1300.47,2379.47 1353.61,2379.47 1360.58,2372.5 1360.58,2336.19 1366.82,2329.95 1436.54,2329.95 CN6.E9@1449,2342.41
NetCN6_J8: CN6.J8 DI.1 | length 466.2
  L1-Top Layer w5: v1(1823.78,2498.94) DI.1@1846.54,2521.7
  L1-Top Layer w10: v2(1462.36,2457) CN6.J8@1474.59,2444.77
  L10-Bottom Layer w5: v2(1462.36,2457) 1475.45,2443.91 1569.84,2443.91 1576.09,2437.66 1576.09,2426.78 1583.96,2418.91 1584.67,2418.91 ; 1584.68,2418.9 1608.39,2418.9 1619.24,2429.75 1708.75,2429.75 1748.5,2469.5 1794.34,2469.5 v1(1823.78,2498.94)
NetCN6_K9: CN6.K9 DO.1 | length 288
  L1-Top Layer w4.5: v2(1529.94,2662) 1538.3,2662 DO.1@1561.87,2685.57
  L1-Top Layer w10: v2(1436.77,2482.59) CN6.K9@1449,2470.36
  L3-SIG1 w4.5: v2(1436.77,2482.59) 1449.41,2495.23 1468.23,2495.23 1475,2502 1475,2607.06 v2(1529.94,2662)
NetCN6_K11: CN6.K11 D.1 | length 160.7
  L1-Top Layer w4: D.1@1248.44,2497.7 1263.07,2483.07 1385.11,2483.07 CN6.K11@1397.82,2470.36
NetCN6_L9: CN6.L9 LR.1 | length 229.7
  L1-Top Layer w5: v2(1436.77,2508.18) CN6.L9@1449,2495.95 ; v2(1481.93,2670) 1490.57,2670 LR.1@1507,2686.43
  L3-SIG1 w5: v2(1436.77,2508.18) 1436.77,2624.85 v2(1481.93,2670)
NetCN6_N9: CN6.N9 MCLK.1 | length 202.3
  L1-Top Layer w4: CN6.N9@1449,2547.13 1448,2548.13 1448,2571 1476.93,2599.93 1542.56,2599.93 1543.32,2600.69 1543.72,2600.69 1572.03,2629 MCLK.1@1602,2629
NetCN8_2: CN8.2 R64.2 R68.2
NetCN9_2: CN9.2 R80.1 R81.1 | length 98.9
  L1-Top Layer w5: R81.1@2228.81,3014.64 R80.1@2228.81,3049.72 2283.72,3049.72 CN9.2@2290,3056
NetCN9_3: CN9.3 R82.1 R83.1 | length 105.6
  L1-Top Layer w4: R83.1@2228.81,2946.98 R82.1@2228.81,2980.98 2264.98,2980.98 CN9.3@2290,3006
NetD1_1: D1.1 Q5.3 | length 76.7
  L1-Top Layer w8: D1.1@44,1711 75,1711 v1(81,1717)
  L10-Bottom Layer w8: Q5.3@44.29,1718.22 79.78,1718.22 v1(81,1717)
NetD1_2: D1.2 R186.1 | length 119.2
  L1-Top Layer w8: D1.2@44,1773.99 v1(83.99,1773.99)
  L10-Bottom Layer w8: R186.1@46,1824.38 68.35,1824.38 83.99,1808.73 v1(83.99,1773.99)
NetD2_1: D2.1 Q4.3 | length 76.7
  L1-Top Layer w8: D2.1@45,1616.5 50.9,1622.4 81.9,1622.4 v1(82,1622.5)
  L10-Bottom Layer w8: Q4.3@45.29,1623.71 80.78,1623.71 v1(82,1622.5)
NetD2_2: D2.2 R185.1 | length 65.9
  L1-Top Layer w10: v2(45.26,1521.13) D2.2@45.26,1553.24
  L10-Bottom Layer w10: R185.1@42.34,1553.71 45.29,1550.76 v2@45.29,1521.16
NetD3_1: D3.1 Q2.3 | length 67.4
  L1-Top Layer w10: v1(36,2376.41) 60.88,2376.41 D3.1@65.36,2380.89
  L10-Bottom Layer w10: v1(36,2376.41) Q2.3@72.2,2376.41
NetD3_2: D3.2 R183.1 | length 80.8
  L1-Top Layer w10: D3.2@65.36,2443.88 93.01,2471.52 v1(110.21,2471.52)
  L10-Bottom Layer w10: R183.1@110.21,2447 v1(110.21,2471.52)
NetD4_1: D4.1 Q3.3 | length 72.7
  L1-Top Layer w10: v1(67.52,2621) 69.33,2619.19 D4.1@69.33,2582.57
  L10-Bottom Layer w10: Q3.3@66.33,2588 67.52,2589.2 v1(67.52,2621)
NetD4_2: D4.2 R182.1 | length 111.8
  L1-Top Layer w10: D4.2@69.33,2519.58 70.75,2521 v1(148,2521)
  L10-Bottom Layer w10: R182.1@117.15,2517 121.15,2521 v1(148,2521)
NetEN_1.35V_1: EN_1.35V.1 R94.2 R100.2 R101.2 U11.1 | length 267.5
  L1-Top Layer w10: EN_1.35V.1@1995.16,2097 EN_1.35V.1@2000,2101.84 v2@2063.03,2101.84
  L10-Bottom Layer w10: R101.2@1965.92,2030.84 1965.92,2085.3 R100.2@1966.5,2085.87 2008.11,2085.87 R94.2@2020,2097.76 2027.24,2105 2029.78,2102.46 v2(2062.59,2102.46) 2062.59,2133.7 2061,2135.29 U11.1@2063.68,2137.98
NetFLASH_CLK_1: FLASH_CLK.1 U1.15 | length 161.4
  L1-Top Layer w4.5: U1.15@920.19,1376.67 983.97,1376.67 998.64,1362 FLASH_CLK.1@1075.53,1362
NetFLASH_CS_1: FLASH_CS.1 U1.14 | length 168.4
  L1-Top Layer w5.5: U1.14@920.19,1326.67 1014.05,1326.67 1043.77,1296.94 FLASH_CS.1@1076.28,1296.94
NetFLASH_MISO_1: FLASH_MISO.1 U1.13 | length 178.1
  L1-Top Layer w5.5: U1.13@920.19,1276.67 998.64,1276.67 1051.7,1223.6 FLASH_MISO.1@1076.28,1223.6
NetFLASH_MOSI_1: FLASH_MOSI.1 U1.17 | length 244.7
  L1-Top Layer w5.5: U1.17@853.26,1426.63 882.63,1456 995.27,1456 1018.27,1433 FLASH_MOSI.1@1076.28,1433
NetIR_EN_1: IR_EN.1 R139.2 U15.7 | length 142.9
  L1-Top Layer w5: v1(990.66,3899) 1008,3881.66 IR_EN.1@1008,3849
  L10-Bottom Layer w5: U15.7@942.4,3953.13 958.47,3953.13 977.6,3934 R139.2@977.6,3926 977.6,3908.34 986.94,3899 v1(990.66,3899)
NetIR_IN1_1: IR_IN1.1 R138.2 U15.6 | length 108.4
  L1-Top Layer w5: v1(997,3990) 1000.23,3990 1008,3982.23 IR_IN1.1@1008,3957.12
  L10-Bottom Layer w5: U15.6@942.4,3972.82 973.72,3972.82 R138.2@977.6,3968.93 977.6,3971.81 996.78,3991 v1@999,3991
NetIR_IN2_1: IR_IN2.1 R140.2 U15.5 | length 110.9
  L1-Top Layer w5: v1(976.35,4041) 976.71,4041.36 IR_IN2.1@976.71,4077
  L10-Bottom Layer w5: U15.5@942.4,3992.5 962.23,3992.5 977,4007.27 R140.2@977,4011 977,4040.35 v1(976.35,4041)
NetJ5_1: J5.1 R89.2 | length 68
  L10-Bottom Layer w10: R89.2@2175.65,1224 2175.65,1289.09 J5.1@2177.7,1291.13
NetJ7_3: J7.3 R74.2 | length 70
  L1-Top Layer w4: J7.3@2025.78,1884.79 R74.2@2025.78,1954.84
NetJ7_4: J7.4 R70.2 | length 70.1
  L1-Top Layer w4.5: J7.4@1925.78,1884.79 1926,1885.01 R70.2@1926,1954.84
NetJ7_5: J7.5 R66.2 | length 70.2
  L1-Top Layer w4: J7.5@1825.78,1884.79 1826.24,1885.25 R66.2@1826.24,1954.84
NetJ7_6: J7.6 R60.2 | length 70.3
  L1-Top Layer w4: R60.2@1725.14,1954.84 1725.14,1885.43 J7.6@1725.78,1884.79
NetJ7_7: J7.7 R58.2 | length 70.5
  L1-Top Layer w4: J7.7@1625.78,1884.79 1626.97,1885.97 R58.2@1626.97,1954.84
NetJ7_8: J7.8 R51.2 | length 79.8
  L1-Top Layer w4.5: R51.2@1525,1964.29 R51.2@1525,1958 1525,1885.57 J7.8@1525.78,1884.79
NetJ7_9: J7.9 R49.2 | length 70.5
  L1-Top Layer w5.5: R49.2@1425,1955 1425,1885.57 J7.9@1425.78,1884.79
NetJ7_10: J7.10 R47.2 | length 85.2
  L1-Top Layer w5.5: J7.10@1325.78,1884.79 1362.42,1921.42 R47.2@1362.42,1954.84
NetJ7_25: J7.25 R65.1 | length 51.8
  L1-Top Layer w5.5: R65.1@1825.78,1733 J7.25@1825.78,1784.79
NetJ8_12: J8.12 R48.1 | length 207.2
  L1-Top Layer w4: R48.1@1377.02,271.81 R48.1@1377.02,268 1377.02,133.54 J8.12@1425.78,84.79
NetJ8_13: J8.13 R50.1 | length 210
  L1-Top Layer w4: R50.1@1483.78,271.81 1477,265.03 1477,133.57 J8.13@1525.78,84.79
NetJ8_14: J8.14 R54.1 | length 206.3
  L1-Top Layer w4: R54.1@1570,268 1570,140.57 J8.14@1625.78,84.79
NetJ8_15: J8.15 R59.1 | length 204.2
  L1-Top Layer w5.5: R59.1@1675,268 1675,135.57 J8.15@1725.78,84.79
NetJ8_18: J8.18 R71.1 | length 205.9
  L1-Top Layer w5.5: R71.1@1972.62,268.7 R71.1@1972.62,268 1972.62,137.94 J8.18@2025.78,84.79
NetJ8_37: J8.37 R69.2 | length 83.9
  L1-Top Layer w5.5: J8.37@1925.78,184.79 R69.2@1925.78,268 R69.2@1925.78,268.7
NetJ8_38: J8.38 R73.2 | length 84
  L1-Top Layer w5.5: R73.2@2025.59,268.7 2025.78,268.51 J8.38@2025.78,184.79
NetJ8_39: J8.39 R75.2 | length 53.5
  L1-Top Layer w5.5: R75.2@2125,238 2125,185.57 J8.39@2125.78,184.79
NetJ8_40: J8.40 R84.2 | length 53.9
  L1-Top Layer w5.5: R84.2@2224.03,238 2224.03,186.54 J8.40@2225.78,184.79
NetJ11_1: J11.1 J11.3 J11.5 R133.2 | length 279.9
  L10-Bottom Layer w5.5: J11.1@968,1638.27 J11.3@1068,1638.27 ; R133.2@1069.97,1717.35 1068,1715.38 J11.3@1068,1638.27 ; J11.5@1168,1638.27 J11.3@1068,1638.27
NetJ13_1: J13.1 R151.2 | length 220.5
  L10-Bottom Layer w5.5: J13.1@544,492 593,443 593,340.29 R151.2@627.29,306
NetL2_1: L2.1 U11.6 | length 129.9
  L10-Bottom Layer w8: U11.6@2116.83,2177.35 2242.41,2177.35 2245.46,2174.3
NetL3_1: L3.1 U13.9
NetL3_2: L3.2 U13.7
NetL4_1: L4.1 U12.9
NetL4_2: L4.2 U12.7
NetL5_1: L5.1 U14.5@1022.79,2241.47
NetL6_1: L6.1 U16.6
NetMEAS_1: MEAS.1 R157.1 R173.1 U20.6 | length 495.4
  L1-Top Layer w4.5: v2(257.24,3246.25) 309.56,3246.25 313,3242.81 454.81,3242.81 484.22,3272.22 MEAS.1@536,3272.22
  L10-Bottom Layer w4.5: U20.6@142.07,3275.17 144.89,3272.35 R173.1@206.57,3272.35 211.93,3272.35 238.03,3246.25 v2(257.24,3246.25) ; v1(473.8,3262.39) 487,3249.19 R157.1@487,3192
NetMEAS_EN_1: MEAS_EN.1 R171.2 U19.3 | length 159.2
  L1-Top Layer w5: v1(232.78,3693.57) 232.78,3706.2 259.15,3732.57 MEAS_EN.1@259.15,3762.54
  L10-Bottom Layer w5: v1(232.78,3693.57) 269.41,3693.57 U19.3@270.29,3692.69
  L10-Bottom Layer w15: U19.3@270.29,3692.69 277,3685.98 R171.2@277,3654
NetQ1_1: Q1.1 R4.2
NetQ2_1: Q2.1 R179.2 | length 34.3
  L10-Bottom Layer w10: Q2.1@142,2402.85 Q2.1@142.85,2402 ; Q2.1@147,2402 147,2402.85 147.3,2403.14 R179.2@147.3,2435
NetQ3_1: Q3.1 R181.2 | length 34.5
  L10-Bottom Layer w10: R181.2@141,2648 141,2613.72 Q3.1@141.13,2613.59
NetQ4_1: Q4.1 R178.2 | length 47.7
  L10-Bottom Layer w5: Q4.1@122.79,1652 128.79,1658 R178.2@168,1658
